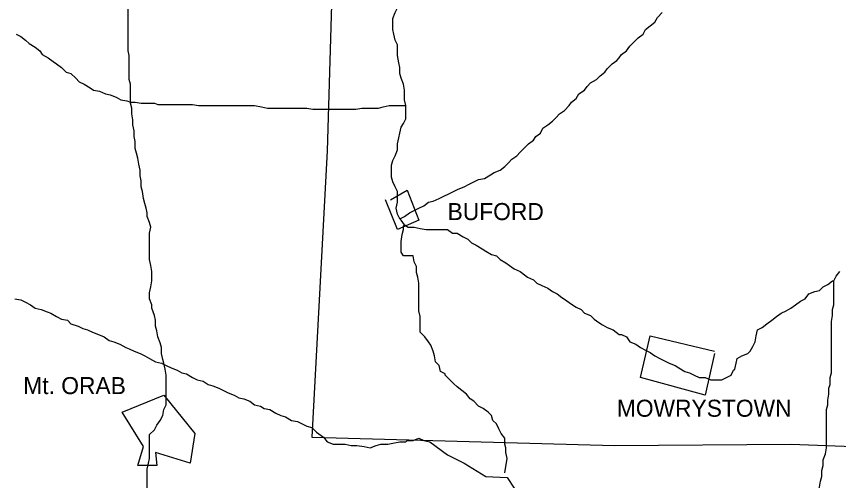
# Model space of a CAD drawing. Extents: x 0 to 40.2, y 0 to 22.
# Drawn here: x 2.608 to 3.548, y 17.685 to 18.216 of the extents above; entities that cross this region are included whole.
import ezdxf

# ---------------------------------------------------------------- set-up
doc = ezdxf.new("R2010")
doc.units = 0
doc.layers.add('Default', color=7, linetype='Continuous')

msp = doc.modelspace()

# ---------------------------------------------------------------- linework, layer by layer
at = {"layer": 'Default'}
for points in [[(2.98345, 18.75772), (2.963, 18.06237), (2.94527, 17.73515), (3.29158, 17.72561), (3.49337, 17.72697), (3.60517, 17.72288), (3.6488, 17.72152)], [(2.73803, 18.11827), (2.73803, 18.12509), (2.73803, 18.13191), (2.73803, 18.13872), (2.73667, 18.14418), (2.73667, 18.15099), (2.73667, 18.15781), (2.73667, 18.16326), (2.73667, 18.17144), (2.73531, 18.1769), (2.73531, 18.18235), (2.73531, 18.18917), (2.73531, 18.19599), (2.73531, 18.2028), (2.73531, 18.20826), (2.73531, 18.21507), (2.73531, 18.22189), (2.73531, 18.22871), (2.73531, 18.23553), (2.73531, 18.24234), (2.73531, 18.24234)], [(3.05299, 18.11418), (3.05162, 18.121), (3.05162, 18.12782), (3.05162, 18.13191), (3.05026, 18.13872), (3.04753, 18.14554), (3.04617, 18.15099), (3.04617, 18.15781), (3.0448, 18.16326), (3.04344, 18.17144), (3.04344, 18.1769), (3.04344, 18.18372), (3.04071, 18.18917), (3.03935, 18.19599), (3.03799, 18.20144), (3.03799, 18.20826), (3.03799, 18.21371), (3.04071, 18.22053), (3.04344, 18.22598), (3.04344, 18.23144)], [(3.29704, 18.16872), (3.29976, 18.17281), (3.30522, 18.1769), (3.30931, 18.18235), (3.31476, 18.18781), (3.31885, 18.1919), (3.32431, 18.19599), (3.32703, 18.20144), (3.33249, 18.20553), (3.33794, 18.20962), (3.34067, 18.21507), (3.34612, 18.22053)], [(2.60715, 18.19599), (2.6126, 18.19326), (2.61805, 18.18917), (2.62214, 18.18508), (2.62896, 18.18099), (2.63441, 18.1769), (2.63714, 18.17281), (2.64396, 18.16872), (2.64941, 18.16463), (2.6535, 18.1619), (2.65896, 18.15781), (2.66441, 18.15236), (2.66986, 18.15099), (2.67532, 18.14554), (2.67941, 18.14145), (2.68486, 18.13872), (2.69168, 18.13463), (2.69577, 18.13191), (2.70259, 18.13054), (2.7094, 18.12782), (2.71486, 18.12645), (2.72167, 18.12373), (2.72713, 18.121), (2.73394, 18.11963), (2.73803, 18.11827), (2.73803, 18.11827)], [(3.17433, 18.05283), (3.17978, 18.05692), (3.18387, 18.06101), (3.18796, 18.0651), (3.19342, 18.07055), (3.19887, 18.07464), (3.2016, 18.07873), (3.20705, 18.08282), (3.20978, 18.08828), (3.21523, 18.09237), (3.22069, 18.09646), (3.22478, 18.10055), (3.22887, 18.10464), (3.23432, 18.10873), (3.23977, 18.11418), (3.2425, 18.11827), (3.24795, 18.12236), (3.25068, 18.12782), (3.2575, 18.13191), (3.26022, 18.136), (3.26432, 18.14009), (3.27113, 18.14418), (3.27522, 18.14827), (3.28068, 18.15236), (3.2834, 18.15645), (3.28886, 18.1619), (3.29431, 18.16599), (3.29704, 18.16872), (3.29704, 18.16872)], [(2.73803, 18.11827), (2.74349, 18.11827), (2.75031, 18.11691), (2.75712, 18.11691), (2.7653, 18.11691), (2.76939, 18.11554), (2.77621, 18.11554), (2.78439, 18.11554), (2.78984, 18.11554), (2.79803, 18.11554), (2.80348, 18.11554), (2.80893, 18.11554), (2.81575, 18.11418), (2.82257, 18.11418), (2.82938, 18.11418), (2.83484, 18.11418), (2.84165, 18.11418), (2.84847, 18.11418), (2.85529, 18.11418), (2.86074, 18.11418), (2.86756, 18.11418), (2.87438, 18.11418), (2.87983, 18.11418), (2.88801, 18.11282), (2.89483, 18.11145), (2.90028, 18.11145), (2.9071, 18.11145), (2.91392, 18.11145), (2.92073, 18.11145), (2.92619, 18.11145), (2.933, 18.11145), (2.93982, 18.11145), (2.94664, 18.11009), (2.95346, 18.11009), (2.95891, 18.11009), (2.963, 18.11009), (2.963, 18.11009)], [(2.75576, 17.99693), (2.7544, 18.00238), (2.75303, 18.00783), (2.75167, 18.01601), (2.75031, 18.02147), (2.75031, 18.02829), (2.74894, 18.03374), (2.74894, 18.04056), (2.74758, 18.04737), (2.74622, 18.05419), (2.74485, 18.05964), (2.74349, 18.0651), (2.74349, 18.07328), (2.74213, 18.07873), (2.74213, 18.08555), (2.74076, 18.09237), (2.74076, 18.09782), (2.7394, 18.10464), (2.7394, 18.11145), (2.73803, 18.11691), (2.73803, 18.11827)], [(2.963, 18.11009), (2.96982, 18.11009), (2.97527, 18.11009), (2.98209, 18.11009), (2.9889, 18.11009), (2.99572, 18.11009), (3.00254, 18.11145), (3.00799, 18.11145), (3.01345, 18.11145), (3.02163, 18.11145), (3.02708, 18.11282), (3.0339, 18.11418), (3.04071, 18.11418), (3.04753, 18.11418), (3.05299, 18.11418)], [(3.04617, 17.98466), (3.04344, 17.99011), (3.04208, 17.99693), (3.04344, 18.00374), (3.04344, 18.0092), (3.04344, 18.01601), (3.04071, 18.02147), (3.03799, 18.02692), (3.03662, 18.03238), (3.03662, 18.04056), (3.03662, 18.04601), (3.03799, 18.05146), (3.04071, 18.05692), (3.04344, 18.06373), (3.04344, 18.07055), (3.0448, 18.07737), (3.04617, 18.08282), (3.04753, 18.08964), (3.05026, 18.09373), (3.05299, 18.09918), (3.05299, 18.106), (3.05299, 18.11145), (3.05299, 18.11418)], [(3.04617, 17.98466), (3.05162, 17.98738), (3.05708, 17.99147), (3.06253, 17.9942), (3.06798, 17.99693), (3.07344, 17.99965), (3.07889, 18.00374), (3.08434, 18.00511), (3.09116, 18.00783), (3.09661, 18.01056), (3.10207, 18.01329), (3.10752, 18.01601), (3.11298, 18.01874), (3.11979, 18.02147), (3.12525, 18.0242), (3.1307, 18.02692), (3.13615, 18.02965), (3.14297, 18.03101), (3.14979, 18.0351), (3.15388, 18.03783), (3.1607, 18.04056), (3.16615, 18.04465), (3.17024, 18.04874), (3.17433, 18.05283), (3.17433, 18.05283)], [(3.03526, 18.00647), (3.05435, 18.01738), (3.06798, 17.98329), (3.04344, 17.97239), (3.02981, 18.00647)], [(2.75985, 17.94239), (2.75985, 17.94921), (2.75985, 17.95602), (2.75985, 17.96148), (2.75985, 17.9683), (2.76121, 17.97511), (2.75985, 17.98057), (2.75712, 17.98738), (2.75712, 17.99147), (2.75576, 17.99693)], [(3.05162, 17.97784), (3.04753, 17.98329), (3.04617, 17.98466)], [(3.06935, 17.86604), (3.06935, 17.87286), (3.06798, 17.87967), (3.06798, 17.88649), (3.06798, 17.89331), (3.06798, 17.89876), (3.06798, 17.90558), (3.06798, 17.91103), (3.06662, 17.91785), (3.06526, 17.9233), (3.06526, 17.93012), (3.06253, 17.93557), (3.06117, 17.94239), (3.05571, 17.94239), (3.05026, 17.94239), (3.04753, 17.94648), (3.04753, 17.9533), (3.04753, 17.95875), (3.04889, 17.96693), (3.05026, 17.97239), (3.05026, 17.97648), (3.05162, 17.97784)], [(3.05162, 17.97784), (3.05571, 17.97511), (3.06253, 17.97511), (3.06935, 17.97375), (3.07616, 17.97239), (3.08162, 17.97239), (3.08707, 17.97239), (3.09389, 17.97239), (3.1007, 17.97239), (3.10616, 17.9683), (3.11161, 17.9683), (3.11843, 17.9642), (3.12388, 17.96148), (3.12797, 17.95739), (3.13343, 17.95466), (3.14024, 17.95057), (3.14433, 17.94784), (3.15115, 17.94375), (3.15661, 17.94239), (3.1607, 17.9383), (3.16751, 17.93421), (3.1716, 17.93148), (3.17706, 17.92739), (3.18387, 17.92467), (3.18524, 17.9233), (3.18524, 17.9233)], [(2.77621, 17.76651), (2.77894, 17.77196), (2.77894, 17.77878), (2.77894, 17.78696), (2.77894, 17.79241), (2.77894, 17.79923), (2.77894, 17.80605), (2.77757, 17.81287), (2.77621, 17.81968), (2.77485, 17.82377), (2.77348, 17.83059), (2.77348, 17.83741), (2.77212, 17.84286), (2.76939, 17.84968), (2.76803, 17.85649), (2.76667, 17.86195), (2.76667, 17.86877), (2.7653, 17.87422), (2.76258, 17.8824), (2.76258, 17.88649), (2.75985, 17.89331), (2.75985, 17.90012), (2.76121, 17.90694), (2.76258, 17.91376), (2.76258, 17.91785), (2.76258, 17.92467), (2.76121, 17.93148), (2.75985, 17.9383), (2.75985, 17.94239), (2.75985, 17.94239)], [(3.54245, 17.91376), (3.54518, 17.91921), (3.54927, 17.92467)], [(3.18524, 17.9233), (3.19205, 17.91785), (3.19887, 17.91512), (3.20296, 17.91103), (3.20841, 17.9083), (3.21523, 17.90558), (3.22069, 17.90149), (3.22614, 17.89876), (3.23159, 17.89467), (3.23568, 17.89194), (3.24114, 17.88785), (3.24795, 17.88376), (3.25341, 17.88104), (3.2575, 17.87695), (3.26432, 17.87422), (3.26841, 17.87013), (3.27386, 17.86604), (3.27795, 17.86331), (3.2834, 17.86058), (3.29022, 17.85786), (3.29704, 17.8524), (3.29976, 17.8524)], [(3.42929, 17.81287), (3.43065, 17.81968), (3.43202, 17.82514), (3.43747, 17.82786), (3.44429, 17.83059), (3.44701, 17.83332), (3.44974, 17.83877), (3.45247, 17.84422), (3.45383, 17.85104), (3.45519, 17.85786), (3.46065, 17.86058), (3.4661, 17.86468), (3.47156, 17.86877), (3.47701, 17.87286), (3.48246, 17.87695), (3.48792, 17.87967), (3.49337, 17.8824), (3.49882, 17.88649), (3.50428, 17.89058), (3.50973, 17.89331), (3.51382, 17.89876), (3.52064, 17.90149), (3.52609, 17.90285), (3.53018, 17.90694), (3.53564, 17.90967), (3.54109, 17.91376), (3.54245, 17.91376)], [(3.53427, 17.72697), (3.53427, 17.73379), (3.53427, 17.73924), (3.53427, 17.74606), (3.53427, 17.75287), (3.53427, 17.75969), (3.53427, 17.76651), (3.53564, 17.77196), (3.53564, 17.77742), (3.537, 17.78423), (3.537, 17.79105), (3.53836, 17.79514), (3.53836, 17.80332), (3.53973, 17.80877), (3.53973, 17.81696), (3.53973, 17.82105), (3.53973, 17.82786), (3.53973, 17.83468), (3.53973, 17.8415), (3.53973, 17.84695), (3.53973, 17.85513), (3.53973, 17.86058), (3.53973, 17.8674), (3.54109, 17.87422), (3.54109, 17.88104), (3.54245, 17.88649), (3.54245, 17.89331), (3.54245, 17.90012), (3.54245, 17.90694), (3.54245, 17.91376), (3.54245, 17.91376)], [(2.60578, 17.89331), (2.6126, 17.89194), (2.61805, 17.88922), (2.62351, 17.88649), (2.62896, 17.8824), (2.63578, 17.88104), (2.6426, 17.87831), (2.64669, 17.87695), (2.6535, 17.87286), (2.65896, 17.87013), (2.66577, 17.86877), (2.66986, 17.86468), (2.67804, 17.86195), (2.6835, 17.85922), (2.68895, 17.85786), (2.69441, 17.85513), (2.70122, 17.8524), (2.70804, 17.84968), (2.71349, 17.84559), (2.71895, 17.84422), (2.72576, 17.8415), (2.73258, 17.83741), (2.73667, 17.83604), (2.74213, 17.83332), (2.74894, 17.83059), (2.7544, 17.82786), (2.75985, 17.82514), (2.76667, 17.82105), (2.77348, 17.81968), (2.77894, 17.81696), (2.78439, 17.81423), (2.79121, 17.8115), (2.79666, 17.80877), (2.80212, 17.80741), (2.80893, 17.80332), (2.81439, 17.80059), (2.8212, 17.79923), (2.82666, 17.79514), (2.83211, 17.79378), (2.83893, 17.79105), (2.84438, 17.78832), (2.84984, 17.7856), (2.85665, 17.78287), (2.86211, 17.78014), (2.86756, 17.77878), (2.87438, 17.77605), (2.87983, 17.77196), (2.88665, 17.7706), (2.89074, 17.76787), (2.89756, 17.76651), (2.90437, 17.76242), (2.90983, 17.75969), (2.91528, 17.75833), (2.9221, 17.75424), (2.92891, 17.75287), (2.93437, 17.75015), (2.93982, 17.74742), (2.94527, 17.74606)], [(3.09798, 17.80741), (3.09252, 17.81014), (3.09116, 17.81696), (3.08707, 17.82105), (3.08571, 17.82786), (3.08434, 17.83332), (3.08162, 17.84013), (3.07889, 17.84422), (3.0748, 17.84968), (3.06935, 17.85513), (3.06935, 17.86058), (3.06935, 17.86468), (3.06935, 17.86604)], [(3.09798, 17.80741), (3.09252, 17.81014), (3.09116, 17.81696), (3.08707, 17.82105), (3.08571, 17.82786), (3.08434, 17.83332), (3.08162, 17.84013), (3.07889, 17.84422), (3.0748, 17.84968), (3.06935, 17.85513), (3.06935, 17.86058), (3.06935, 17.86468), (3.06935, 17.86604)], [(3.29976, 17.8524), (3.30522, 17.84968), (3.30931, 17.84422), (3.31613, 17.8415), (3.32158, 17.83741), (3.32703, 17.83468), (3.33249, 17.83195), (3.33794, 17.82786), (3.34339, 17.82514), (3.34885, 17.82241), (3.3543, 17.81968), (3.36112, 17.81696), (3.36521, 17.81423), (3.37203, 17.81014), (3.37748, 17.80877), (3.38293, 17.80605), (3.38839, 17.80332), (3.3952, 17.80332), (3.40202, 17.80059), (3.40747, 17.80059), (3.41429, 17.80059), (3.41975, 17.80332), (3.4252, 17.80605), (3.42793, 17.8115), (3.42793, 17.8115), (3.42929, 17.81287)], [(3.40611, 17.83059), (3.3952, 17.78287), (3.32158, 17.80332), (3.33249, 17.85104), (3.40611, 17.83332)], [(3.16615, 17.72697), (3.16615, 17.73379), (3.16206, 17.73924), (3.15933, 17.74469), (3.15661, 17.75015), (3.15251, 17.75424), (3.15115, 17.75969), (3.14706, 17.76378), (3.14161, 17.76787), (3.13615, 17.7706), (3.1307, 17.77605), (3.12661, 17.77878), (3.12252, 17.78423), (3.11707, 17.78832), (3.11161, 17.79241), (3.10752, 17.7965), (3.10343, 17.80059), (3.09798, 17.80605), (3.09798, 17.80741)], [(3.16615, 17.72697), (3.16615, 17.73379), (3.16206, 17.73924), (3.15933, 17.74469), (3.15661, 17.75015), (3.15251, 17.75424), (3.15115, 17.75969), (3.14706, 17.76378), (3.14161, 17.76787), (3.13615, 17.7706), (3.1307, 17.77605), (3.12661, 17.77878), (3.12252, 17.78423), (3.11707, 17.78832), (3.11161, 17.79241), (3.10752, 17.7965), (3.10343, 17.80059), (3.09798, 17.80605), (3.09798, 17.80741)], [(2.77621, 17.78287), (2.81166, 17.73924), (2.80621, 17.70515), (2.76667, 17.71743), (2.76803, 17.70243), (2.74622, 17.70243), (2.75303, 17.72424), (2.72849, 17.76378), (2.77621, 17.78287)], [(2.76667, 17.63562), (2.76667, 17.64107), (2.7653, 17.64789), (2.76258, 17.65334), (2.75985, 17.66016), (2.75985, 17.66562), (2.75712, 17.67243), (2.75712, 17.67925), (2.75712, 17.68607), (2.75712, 17.69288), (2.75712, 17.69834), (2.75849, 17.70515), (2.75985, 17.71061), (2.75985, 17.71743), (2.75985, 17.72561), (2.75985, 17.73106), (2.75985, 17.73788), (2.7653, 17.74333), (2.76803, 17.74878), (2.77212, 17.75424), (2.77485, 17.75969), (2.77621, 17.76651), (2.77621, 17.76651)], [(2.94527, 17.74606), (2.95073, 17.7406), (2.95891, 17.73515)], [(2.95891, 17.73515), (2.963, 17.7297), (2.96982, 17.72697), (2.978, 17.72697), (2.98345, 17.72697), (2.99027, 17.72561), (2.99708, 17.72561), (3.00527, 17.72424), (3.01208, 17.72288), (3.0189, 17.72561), (3.02435, 17.72697), (3.03253, 17.72697), (3.03799, 17.72833), (3.04617, 17.7297), (3.05299, 17.7297), (3.05435, 17.73106)], [(3.05435, 17.73106), (3.06117, 17.73106), (3.06798, 17.73379), (3.07344, 17.73106), (3.08025, 17.7297)], [(3.08025, 17.7297), (3.1007, 17.7147), (3.11979, 17.70515), (3.14433, 17.69016), (3.16888, 17.68879), (3.17706, 17.67652), (3.2166, 17.65334), (3.25886, 17.61653), (3.29431, 17.5879), (3.34612, 17.562), (3.3693, 17.54563), (3.39929, 17.50882), (3.44156, 17.49655), (3.45656, 17.48973)], [(3.16615, 17.69425), (3.16888, 17.71061), (3.16751, 17.71743), (3.16751, 17.72288), (3.16615, 17.72697)], [(3.49882, 17.59335), (3.49882, 17.59881), (3.50155, 17.60563), (3.50291, 17.61108), (3.50428, 17.61653), (3.50564, 17.62335), (3.50973, 17.63017), (3.51109, 17.63562), (3.51518, 17.64107), (3.51791, 17.64789), (3.51927, 17.65334), (3.52064, 17.6588), (3.522, 17.66562), (3.52337, 17.67243), (3.52609, 17.67789), (3.52746, 17.6847), (3.52882, 17.69016), (3.52882, 17.69697), (3.53018, 17.70243), (3.53018, 17.70925), (3.53291, 17.71606), (3.53427, 17.72288), (3.53427, 17.72697)]]:
    msp.add_lwpolyline(points, dxfattribs=at)

# ---------------------------------------------------------------- texts
for s, p in [('BUFORD', (3.1007, 17.98329)), ('Mt. ORAB', (2.61533, 17.78423)), ('MOWRYSTOWN', (3.29431, 17.75833))]:
    msp.add_text(s, height=0.019502, dxfattribs=at).set_placement(p)

doc.saveas('drawing.dxf')
